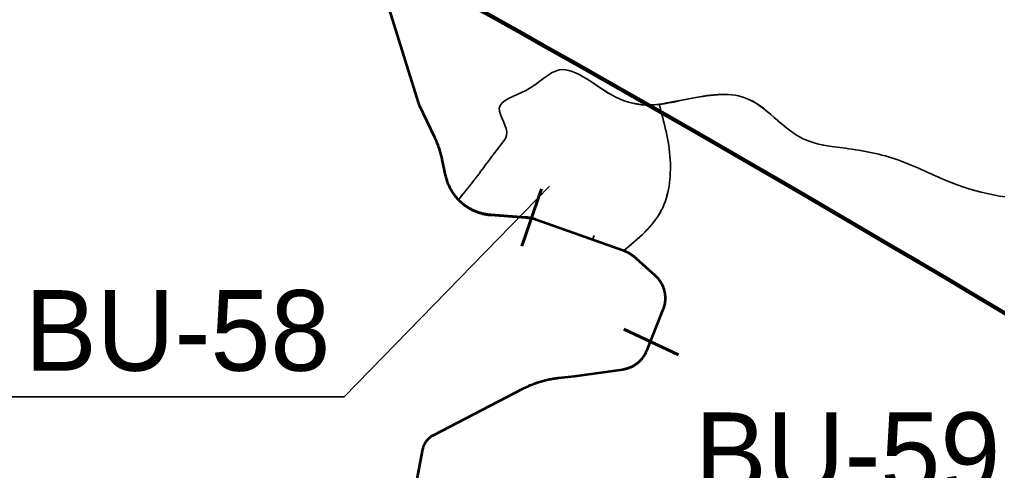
# Model space of a CAD drawing. Extents: x 553962 to 842807, y 8883888 to 9032388.
# Drawn here: x 651261 to 656115, y 8962565 to 8964803 of the extents above; entities that cross this region are included whole.
import ezdxf

# ---------------------------------------------------------------- set-up
doc = ezdxf.new("R2010")
doc.units = 0
doc.header["$LTSCALE"] = 150
for name, color, linetype, lineweight in [('20', 7, 'Continuous', 35), ('40', 7, 'Continuous', 60), ('60', 7, 'Continuous', 53), ('9', 7, 'Continuous', 90)]:
    doc.layers.add(name, color=color, linetype=linetype, lineweight=lineweight)

msp = doc.modelspace()

# ---------------------------------------------------------------- linework, layer by layer
at = {"layer": '20'}
for p, q in [((654435.2, 8964383.2), (654438.6, 8964383.2)), ((653468.6, 8963882.6), (653439.4, 8963908.4)), ((654105.5, 8963710.2), (654112.9, 8963730.9))]:
    msp.add_line(p, q, dxfattribs=at)
for points in [[(654260.7, 8963654.9), (654257.2, 8963656.2), (654254.9, 8963657.1), (653825.5, 8963809.7), (653821.7, 8963811.1), (653817.9, 8963812.3), (653814.1, 8963813.4), (653810.2, 8963814.5), (653806.3, 8963815.5), (653802.5, 8963816.4), (653798.5, 8963817.2), (653794.6, 8963818), (653790.7, 8963818.7), (653786.7, 8963819.3), (653782.8, 8963819.8), (653778.8, 8963820.3), (653774.8, 8963820.6), (653772.9, 8963820.8), (653600.8, 8963833.2), (653596.4, 8963833.5), (653591.9, 8963834), (653587.5, 8963834.5), (653583.1, 8963835.1), (653578.6, 8963835.8), (653574.2, 8963836.5), (653569.8, 8963837.4), (653565.5, 8963838.3), (653561.1, 8963839.3), (653556.8, 8963840.3), (653552.4, 8963841.5), (653548.1, 8963842.7), (653543.8, 8963844), (653539.6, 8963845.4), (653535.4, 8963846.8), (653531.2, 8963848.4), (653527, 8963850), (653522.8, 8963851.7), (653518.7, 8963853.4), (653514.7, 8963855.2), (653510.6, 8963857.1), (653506.6, 8963859.1), (653502.6, 8963861.2), (653498.7, 8963863.3), (653494.8, 8963865.5), (653490.9, 8963867.7), (653487.1, 8963870), (653483.3, 8963872.4), (653479.6, 8963874.9), (653475.9, 8963877.4), (653472.2, 8963880), (653468.6, 8963882.6)], [(654465.8, 8963438.1), (654465.4, 8963441.6), (654464.8, 8963445), (654464.2, 8963448.4), (654463.5, 8963451.8), (654462.7, 8963455.1), (654461.8, 8963458.5), (654460.9, 8963461.8), (654459.9, 8963465.2), (654458.8, 8963468.4), (654457.6, 8963471.7), (654456.4, 8963474.9), (654455.1, 8963478.1), (654453.7, 8963481.3), (654452.2, 8963484.4), (654450.7, 8963487.6), (654449.1, 8963490.6), (654447.4, 8963493.7), (654445.6, 8963496.6), (654443.8, 8963499.6), (654441.9, 8963502.5), (654440, 8963505.4), (654438, 8963508.2), (654435.9, 8963511), (654433.8, 8963513.7), (654431.6, 8963516.3), (654429.3, 8963519), (654427, 8963521.5), (654424.6, 8963524), (654422.1, 8963526.5), (654419.6, 8963528.9), (654417.5, 8963530.9), (654321.9, 8963617.2), (654318.9, 8963619.8), (654315.8, 8963622.4), (654312.7, 8963624.9), (654309.6, 8963627.4), (654306.4, 8963629.8), (654303.1, 8963632.1), (654299.8, 8963634.4), (654296.5, 8963636.6), (654293.1, 8963638.7), (654289.7, 8963640.8), (654286.2, 8963642.8), (654282.7, 8963644.7), (654279.2, 8963646.6), (654275.6, 8963648.4), (654272, 8963650.1), (654268.3, 8963651.8), (654264.7, 8963653.3), (654263.2, 8963653.9)], [(653766.2, 8962974.6), (653771.8, 8962977.4), (653777.5, 8962980.1), (653783.3, 8962982.8), (653789, 8962985.4), (653794.8, 8962987.9), (653800.7, 8962990.3), (653806.5, 8962992.7), (653812.4, 8962995), (653818.3, 8962997.2), (653824.3, 8962999.3), (653830.3, 8963001.4), (653836.3, 8963003.4), (653842.3, 8963005.3), (653848.4, 8963007.2), (653854.4, 8963008.9), (653860.5, 8963010.6), (653866.7, 8963012.2), (653872.8, 8963013.8), (653878.9, 8963015.2), (653885.1, 8963016.6), (653891.3, 8963017.9), (653897.5, 8963019.1), (653903.7, 8963020.2), (653910, 8963021.3), (653916.2, 8963022.3), (653922.5, 8963023.2), (653928.7, 8963024), (653935, 8963024.8), (653936.5, 8963024.9), (654015, 8963033.5), (654255.5, 8963067.1), (654258.9, 8963067.7), (654262.3, 8963068.3), (654265.7, 8963068.9), (654269.1, 8963069.7), (654272.5, 8963070.5), (654275.8, 8963071.4), (654279.1, 8963072.4), (654282.4, 8963073.5), (654285.7, 8963074.6), (654288.9, 8963075.8), (654292.2, 8963077.1), (654295.3, 8963078.5), (654298.5, 8963079.9), (654301.6, 8963081.5), (654304.7, 8963083), (654307.7, 8963084.7), (654310.7, 8963086.4), (654313.7, 8963088.2), (654316.6, 8963090.1), (654319.5, 8963092), (654322.3, 8963094), (654325.1, 8963096), (654327.9, 8963098.2), (654330.6, 8963100.3), (654333.2, 8963102.6), (654335.8, 8963104.9), (654338.3, 8963107.2), (654340.8, 8963109.7), (654343.2, 8963112.2), (654345.6, 8963114.7), (654347.9, 8963117.3), (654350.1, 8963119.9), (654352.3, 8963122.6), (654354.4, 8963125.3), (654356.5, 8963128.1), (654358.5, 8963131), (654360.4, 8963133.8), (654362.2, 8963136.8), (654364, 8963139.7), (654365.8, 8963142.7), (654367.4, 8963145.8), (654369, 8963148.9), (654370.5, 8963152), (654371.9, 8963155.1), (654373.3, 8963158.3), (654373.8, 8963159.5), (654456.1, 8963363.4), (654457.3, 8963366.6), (654458.5, 8963369.8), (654459.6, 8963373.1), (654460.7, 8963376.4), (654461.6, 8963379.8), (654462.5, 8963383.1), (654463.3, 8963386.5), (654464, 8963389.9), (654464.7, 8963393.3), (654465.2, 8963396.7), (654465.7, 8963400.1), (654466.1, 8963403.6), (654466.5, 8963407), (654466.7, 8963410.5), (654466.9, 8963413.9), (654467, 8963417.4), (654467, 8963420.8), (654466.9, 8963424.3), (654466.8, 8963427.8), (654466.5, 8963431.2), (654466.2, 8963434.7), (654465.8, 8963438.1)], [(653231.9, 8962505.4), (653263.2, 8962670.7), (653263.7, 8962673.5), (653264.4, 8962676.2), (653265.1, 8962678.9), (653265.9, 8962681.7), (653266.8, 8962684.3), (653267.7, 8962687), (653268.8, 8962689.7), (653269.9, 8962692.2), (653271, 8962694.8), (653272.3, 8962697.4), (653273.6, 8962699.9), (653275, 8962702.3), (653276.4, 8962704.8), (653278, 8962707.1), (653279.6, 8962709.5), (653281.2, 8962711.8), (653282.9, 8962714), (653284.7, 8962716.2), (653286.6, 8962718.4), (653288.5, 8962720.5), (653290.4, 8962722.5), (653292.4, 8962724.5), (653294.5, 8962726.4), (653296.6, 8962728.2), (653298.8, 8962730.1), (653301.1, 8962731.8), (653303.3, 8962733.5), (653305.7, 8962735.1), (653308, 8962736.6), (653310.4, 8962738.1), (653312.9, 8962739.5), (653315.4, 8962740.8), (653315.4, 8962740.8), (653760.5, 8962971.7), (653766.2, 8962974.6)]]:
    msp.add_lwpolyline(points, dxfattribs=at)
for points in [[(653439.4, 8963908.4), (653526, 8964017.2), (653652.9, 8964185.6), (653677.8, 8964227.3), (653642, 8964362.4), (653774.2, 8964450.7), (653939.5, 8964552.7), (654220.6, 8964417.6), (654388.7, 8964379), (654435.3, 8964382.7)], [(653439.4, 8963908.4), (653526, 8964017.2), (653652.9, 8964185.6), (653677.8, 8964227.3), (653642, 8964362.4), (653774.2, 8964450.7), (653939.5, 8964552.7), (654220.6, 8964417.6), (654388.7, 8964379), (654583.2, 8964409.3), (654861.5, 8964414.8), (655150.8, 8964210.8), (655360.2, 8964163.9), (655620.3, 8964106.6), (655884.8, 8963993.5), (656372.6, 8963913.6), (656631.6, 8963960.5), (656882.3, 8964021.1), (657228.1, 8963897), (657481.6, 8963841.9), (657691, 8963910.8), (657809.5, 8964029.4), (657836.5, 8964054.2)], [(654438.6, 8964383.2), (654583.2, 8964409.3), (654861.5, 8964414.8), (655150.8, 8964210.8), (655360.2, 8964163.9), (655620.3, 8964106.6), (655884.8, 8963993.5), (656372.6, 8963913.6), (656631.6, 8963960.5), (656882.3, 8964021.1), (657228.1, 8963897), (657481.6, 8963841.9), (657691, 8963910.8), (657809.5, 8964029.4), (657836.5, 8964054.2)], [(654257.1, 8963653.4), (654446.2, 8963855.2), (654490.3, 8964107.5), (654435.2, 8964383.2)], [(654435.2, 8964383.2), (654490.3, 8964107.5), (654446.2, 8963855.2), (654259, 8963655.4)], [(654259, 8963655.4), (654446.2, 8963855.2), (654490.3, 8964107.5), (654435.2, 8964383.2)]]:
    msp.add_spline(points, degree=3, dxfattribs=at)
at = {"layer": '40'}
for p, q in [((653753.5, 8963678.8), (653852.1, 8963962.1)), ((654259.7, 8963267), (654531.2, 8963139.3))]:
    msp.add_line(p, q, dxfattribs=at)
at = {"layer": '40', "lineweight": 35}
msp.add_lwpolyline([(653891.6, 8963975.3), (652872.2, 8962931), (651027.4, 8962931)], dxfattribs=at)
at = {"layer": '60'}
for points in [[(653054.3, 8964986.9), (653240.1, 8964391.1), (653241, 8964388.4), (653241.9, 8964385.8), (653243, 8964383.2), (653244.1, 8964380.5), (653245.2, 8964378.1), (653320.3, 8964219.5), (653323, 8964213.8), (653325.6, 8964208), (653328.1, 8964202.2)], [(653328.1, 8964202.2), (653330.6, 8964196.4), (653332.9, 8964190.6), (653335.2, 8964184.7), (653337.5, 8964178.8), (653339.6, 8964172.8), (653341.7, 8964166.8), (653343.7, 8964160.8), (653345.6, 8964154.8), (653347.5, 8964148.8), (653349.2, 8964142.7), (653351, 8964136.6), (653352.6, 8964130.5), (653354.1, 8964124.3), (653355.6, 8964118.2), (653357, 8964112), (653357.6, 8964109.1), (653374.2, 8964030.7), (653375.2, 8964026.3), (653376.2, 8964022), (653377.3, 8964017.6), (653378.6, 8964013.3), (653379.8, 8964009), (653381.2, 8964004.8), (653382.6, 8964000.5), (653384.1, 8963996.3), (653385.7, 8963992.1), (653387.3, 8963988), (653389.1, 8963983.9), (653390.9, 8963979.8), (653392.8, 8963975.7), (653394.7, 8963971.7), (653396.7, 8963967.7), (653398.8, 8963963.7), (653401, 8963959.8), (653403.2, 8963955.9), (653405.5, 8963952.1), (653407.9, 8963948.3), (653410.3, 8963944.6), (653412.8, 8963940.8), (653415.4, 8963937.2), (653418, 8963933.6), (653420.7, 8963930), (653423.5, 8963926.5), (653426.3, 8963923), (653429.2, 8963919.6), (653432.1, 8963916.2), (653435.1, 8963912.9), (653438.2, 8963909.7), (653441.3, 8963906.5), (653444.5, 8963903.3), (653447.7, 8963900.2), (653451, 8963897.2), (653454.3, 8963894.2), (653457.7, 8963891.3), (653461.2, 8963888.5), (653464.7, 8963885.7), (653468.2, 8963883), (653471.8, 8963880.3), (653475.5, 8963877.7), (653479.1, 8963875.2), (653482.9, 8963872.7), (653486.6, 8963870.3), (653490.5, 8963868), (653494.3, 8963865.7), (653498.2, 8963863.5), (653502.2, 8963861.4), (653506.1, 8963859.3), (653510.1, 8963857.4), (653514.2, 8963855.5), (653518.3, 8963853.6), (653522.4, 8963851.9), (653526.5, 8963850.2), (653530.7, 8963848.6), (653534.9, 8963847), (653539.1, 8963845.6), (653543.4, 8963844.2), (653547.6, 8963842.9), (653551.9, 8963841.6), (653556.2, 8963840.5), (653560.6, 8963839.4), (653565, 8963838.4), (653569.3, 8963837.5), (653573.7, 8963836.6), (653578.1, 8963835.8), (653582.5, 8963835.2), (653587, 8963834.6), (653591.4, 8963834), (653595.9, 8963833.6), (653600.3, 8963833.2), (653600.8, 8963833.2), (653772.9, 8963820.8), (653776.8, 8963820.5), (653780.8, 8963820.1), (653784.8, 8963819.6), (653788.8, 8963819), (653792.7, 8963818.3), (653796.6, 8963817.6), (653800.6, 8963816.8), (653804.5, 8963816), (653808.3, 8963815)], [(654465.8, 8963438.1), (654465.4, 8963441.6), (654464.8, 8963445), (654464.2, 8963448.4), (654463.5, 8963451.8), (654462.7, 8963455.1), (654461.8, 8963458.5), (654460.9, 8963461.8), (654459.9, 8963465.2), (654458.8, 8963468.4), (654457.6, 8963471.7), (654456.4, 8963474.9), (654455.1, 8963478.1), (654453.7, 8963481.3), (654452.2, 8963484.4), (654450.7, 8963487.6), (654449.1, 8963490.6), (654447.4, 8963493.7), (654445.6, 8963496.6), (654443.8, 8963499.6), (654441.9, 8963502.5), (654440, 8963505.4), (654438, 8963508.2), (654435.9, 8963511), (654433.8, 8963513.7), (654431.6, 8963516.3), (654429.3, 8963519), (654427, 8963521.5), (654424.6, 8963524), (654422.1, 8963526.5), (654419.6, 8963528.9), (654417.5, 8963530.9), (654321.9, 8963617.2), (654318.9, 8963619.8), (654315.8, 8963622.4), (654312.7, 8963624.9), (654309.6, 8963627.4), (654306.4, 8963629.8), (654303.1, 8963632.1), (654299.8, 8963634.4), (654296.5, 8963636.6), (654293.1, 8963638.7), (654289.7, 8963640.8), (654286.2, 8963642.8), (654282.7, 8963644.7), (654279.2, 8963646.6), (654275.6, 8963648.4), (654272, 8963650.1), (654268.3, 8963651.8), (654264.7, 8963653.3), (654261, 8963654.8), (654257.2, 8963656.2), (654254.9, 8963657.1), (653825.5, 8963809.7), (653821.7, 8963811.1), (653817.9, 8963812.3), (653814.1, 8963813.4), (653810.2, 8963814.5), (653806.3, 8963815.5), (653802.5, 8963816.4), (653798.5, 8963817.2), (653794.6, 8963818), (653790.7, 8963818.7), (653786.7, 8963819.3), (653782.8, 8963819.8), (653778.8, 8963820.3), (653774.8, 8963820.6), (653772.9, 8963820.8), (653600.8, 8963833.2), (653596.4, 8963833.5), (653591.9, 8963834), (653587.5, 8963834.5), (653583.1, 8963835.1), (653578.6, 8963835.8), (653574.2, 8963836.5), (653569.8, 8963837.4), (653565.5, 8963838.3), (653561.1, 8963839.3), (653556.8, 8963840.3), (653552.4, 8963841.5), (653548.1, 8963842.7), (653543.8, 8963844), (653539.6, 8963845.4), (653535.4, 8963846.8), (653531.2, 8963848.4), (653527, 8963850), (653522.8, 8963851.7), (653518.7, 8963853.4), (653514.7, 8963855.2), (653510.6, 8963857.1), (653506.6, 8963859.1), (653502.6, 8963861.2), (653498.7, 8963863.3), (653494.8, 8963865.5), (653490.9, 8963867.7), (653487.1, 8963870), (653483.3, 8963872.4), (653479.6, 8963874.9), (653475.9, 8963877.4), (653472.2, 8963880), (653468.6, 8963882.6)], [(653766.2, 8962974.6), (653771.8, 8962977.4), (653777.5, 8962980.1), (653783.3, 8962982.8), (653789, 8962985.4), (653794.8, 8962987.9), (653800.7, 8962990.3), (653806.5, 8962992.7), (653812.4, 8962995), (653818.3, 8962997.2), (653824.3, 8962999.3), (653830.3, 8963001.4), (653836.3, 8963003.4), (653842.3, 8963005.3), (653848.4, 8963007.2), (653854.4, 8963008.9), (653860.5, 8963010.6), (653866.7, 8963012.2), (653872.8, 8963013.8), (653878.9, 8963015.2), (653885.1, 8963016.6), (653891.3, 8963017.9), (653897.5, 8963019.1), (653903.7, 8963020.2), (653910, 8963021.3), (653916.2, 8963022.3), (653922.5, 8963023.2), (653928.7, 8963024), (653935, 8963024.8), (653936.5, 8963024.9), (654015, 8963033.5), (654255.5, 8963067.1), (654258.9, 8963067.7), (654262.3, 8963068.3), (654265.7, 8963068.9), (654269.1, 8963069.7), (654272.5, 8963070.5), (654275.8, 8963071.4), (654279.1, 8963072.4), (654282.4, 8963073.5), (654285.7, 8963074.6), (654288.9, 8963075.8), (654292.2, 8963077.1), (654295.3, 8963078.5), (654298.5, 8963079.9), (654301.6, 8963081.5), (654304.7, 8963083), (654307.7, 8963084.7), (654310.7, 8963086.4), (654313.7, 8963088.2), (654316.6, 8963090.1), (654319.5, 8963092), (654322.3, 8963094), (654325.1, 8963096), (654327.9, 8963098.2), (654330.6, 8963100.3), (654333.2, 8963102.6), (654335.8, 8963104.9), (654338.3, 8963107.2), (654340.8, 8963109.7), (654343.2, 8963112.2), (654345.6, 8963114.7), (654347.9, 8963117.3), (654350.1, 8963119.9), (654352.3, 8963122.6), (654354.4, 8963125.3), (654356.5, 8963128.1), (654358.5, 8963131), (654360.4, 8963133.8), (654362.2, 8963136.8), (654364, 8963139.7), (654365.8, 8963142.7), (654367.4, 8963145.8), (654369, 8963148.9), (654370.5, 8963152), (654371.9, 8963155.1), (654373.3, 8963158.3), (654373.8, 8963159.5), (654456.1, 8963363.4), (654457.3, 8963366.6), (654458.5, 8963369.8), (654459.6, 8963373.1), (654460.7, 8963376.4), (654461.6, 8963379.8), (654462.5, 8963383.1), (654463.3, 8963386.5), (654464, 8963389.9), (654464.7, 8963393.3), (654465.2, 8963396.7), (654465.7, 8963400.1), (654466.1, 8963403.6), (654466.5, 8963407), (654466.7, 8963410.5), (654466.9, 8963413.9), (654467, 8963417.4), (654467, 8963420.8), (654466.9, 8963424.3), (654466.8, 8963427.8), (654466.5, 8963431.2), (654466.2, 8963434.7), (654465.8, 8963438.1)], [(653187, 8962268.5), (653263.2, 8962670.7), (653263.7, 8962673.5), (653264.4, 8962676.2), (653265.1, 8962678.9), (653265.9, 8962681.7), (653266.8, 8962684.3), (653267.7, 8962687), (653268.8, 8962689.7), (653269.9, 8962692.2), (653271, 8962694.8), (653272.3, 8962697.4), (653273.6, 8962699.9), (653275, 8962702.3), (653276.4, 8962704.8), (653278, 8962707.1), (653279.6, 8962709.5), (653281.2, 8962711.8), (653282.9, 8962714), (653284.7, 8962716.2), (653286.6, 8962718.4), (653288.5, 8962720.5), (653290.4, 8962722.5), (653292.4, 8962724.5), (653294.5, 8962726.4), (653296.6, 8962728.2), (653298.8, 8962730.1), (653301.1, 8962731.8), (653303.3, 8962733.5), (653305.7, 8962735.1), (653308, 8962736.6), (653310.4, 8962738.1), (653312.9, 8962739.5), (653315.4, 8962740.8), (653315.4, 8962740.8), (653760.5, 8962971.7), (653766.2, 8962974.6)]]:
    msp.add_lwpolyline(points, dxfattribs=at)
at = {"layer": '9'}
msp.add_spline([(637260.6, 8972975.8), (641524.5, 8971056.2), (652526.1, 8965412.7), (653164.3, 8965062.8), (670790.5, 8953770.1), (686194, 8943929.9), (696283.3, 8937647.1)], degree=3, dxfattribs=at)

# ---------------------------------------------------------------- texts
at = {"layer": '40'}
for s, p in [('BU-58', (651287.5, 8963060.3)), ('BU-59', (654612.6, 8962453.1))]:
    msp.add_text(s, height=400, dxfattribs=at).set_placement(p)

doc.saveas('drawing.dxf')
